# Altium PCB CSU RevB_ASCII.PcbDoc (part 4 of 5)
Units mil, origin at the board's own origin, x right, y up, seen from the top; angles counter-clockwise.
Board outline 5905.51 x 4330.71 mil, 8 copper layers (Top Layer, InternalPlane1, MidLayer1, InternalPlane2, MidLayer2, InternalPlane3, MidLayer3, Bottom Layer); 265 components, 387 nets, 1910 pads, 1151 vias.
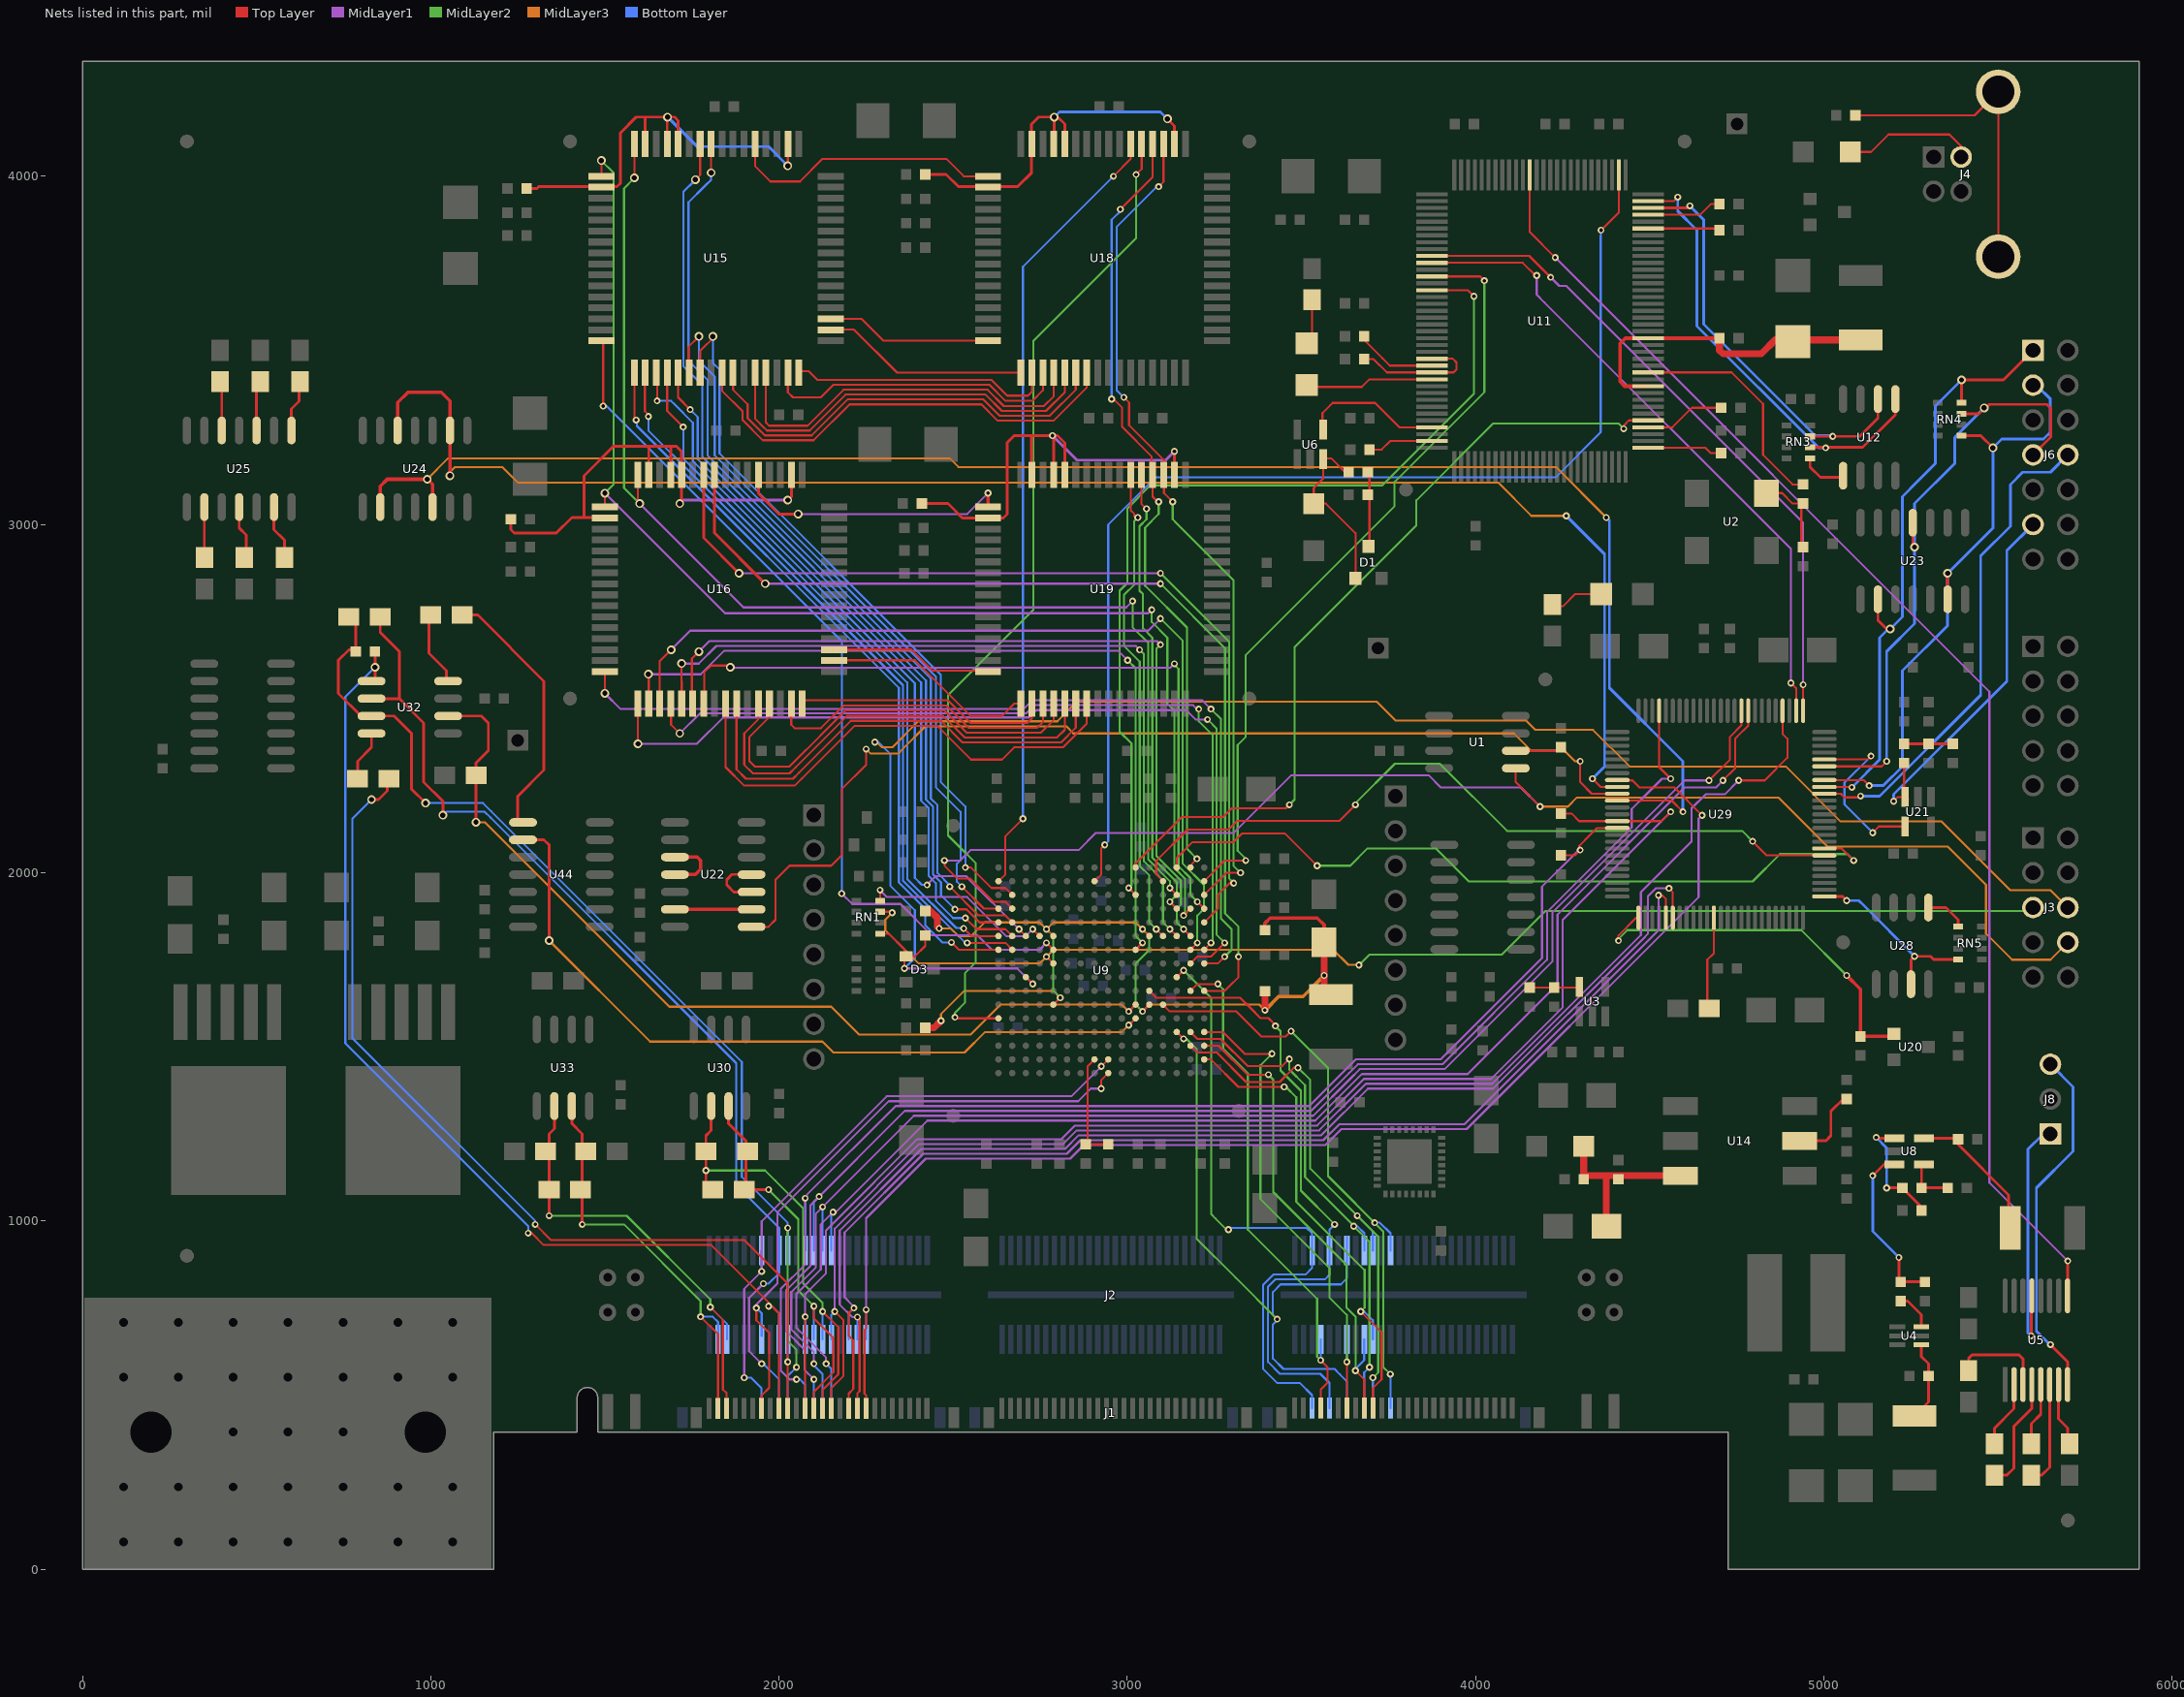
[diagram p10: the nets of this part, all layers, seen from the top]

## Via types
v1: diameter 20, hole 10, Top Layer to Bottom Layer, 647 vias
v2: diameter 25, hole 15, Top Layer to Bottom Layer, 352 vias
v3: diameter 20, hole 10, Top Layer to Bottom Layer, tented top, 151 vias
v4: diameter 20, hole 10, Top Layer to Bottom Layer, tented bottom, 1 vias

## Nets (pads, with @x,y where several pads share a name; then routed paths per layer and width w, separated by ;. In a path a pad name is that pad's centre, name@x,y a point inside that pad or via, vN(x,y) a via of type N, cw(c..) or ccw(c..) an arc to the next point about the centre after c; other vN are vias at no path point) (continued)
MPP: J1.45 J2.45 U9.K15 | length 1502.6
  Top Layer w6: U9.K15@3181.18,1660.67 3200.87,1680.35 v1(3259.92,1680.35) ; v1(3555,600) 3575,580 3575,535 3555,515 3555,463.05 J1.45@3555.21,462.85
  MidLayer2 w6: v1(3259.92,1680.35) 3275,1665.28 3275,1495 3346,1424 3346,974.91 3545,775.91 3545,610 v1(3555,600)
  Bottom Layer w6: v1@3555.51,600.51 J2.45@3555.51,659.84
N_CONFIG: J3.5 RN1.3 U9.H5 | length 3559.7
  Top Layer w6: RN1.3@2290.01,1887.99 2322.01,1887.99 v1(2325,1885) ; v3(2767.8,1759.09) U9.H5@2787.48,1739.41
  MidLayer2 w6: v1(3665,1735) 3695,1765 4075,1765 4200,1890 5590,1890 J3.5@5600,1900
  MidLayer3 w6: v1(2325,1885) 2305,1865 2305,1835 2400.59,1739.41 2748.11,1739.41 2787.48,1778.78 3591.22,1778.78 3634.57,1735.43 3664.57,1735.43 v1(3665,1735)
NCE: C14.1 D3.1 J3.6 RN1.1 U9.J3 | length 5107
  Top Layer w6: RN1.1@2290.01,1825 2315,1825 2360,1780 v1(2360,1725) ; D3.1@2360,1760 2390,1760 2420,1790 C14.1@2420,1820.01 ; U9.J3@2708.74,1700.04 v3(2728.43,1680.35)
  MidLayer1 w6: v1(2360,1725) 2683.78,1725 2716.44,1692.34 v3(2728.43,1680.35)
  MidLayer3 w6: v1(2275,2375) 2280,2375 2295,2360 2325,2360 2400,2435 2799,2435 2855,2491 3715.9,2491 3770,2436.9 4145,2436.9 4171.9,2410 4336.97,2410 4441.97,2305 4890,2305 5048,2147 5338,2147 5535,1950 5650,1950 J3.6@5700,1900
  Bottom Layer w6: v1(2275,2375) 2285,2375 2320,2340 2320,1962.12 2390,1892.12 2390,1755 v1(2360,1725)
NCS: J3.8 U1.1 U9.D2 | length 4069.6
  Top Layer w6: v1(2475,2035) 2475,2020 2512,1983 2549,1983 2615.43,1916.57 2649.68,1916.57 U9.D2@2669.37,1896.89 ; U1.1@4115,2300 4115,2260 v1(4185,2190)
  MidLayer1 w6: v1(2475,2035) 2520,2035 2550,2065 2860,2065 2909.54,2114.54 3305.46,2114.54 3470.91,2280 3865,2280 3900,2245 4130,2245 v1(4185,2190)
  MidLayer3 w6: v1(4185,2190) 4265,2190 4291,2216 4869,2216 5010,2075 5355,2075 5465,1965 5465,1825 5540,1750 5650,1750 J3.8@5700,1800
NetC2_1: C2.1 D1.1 R3.2 U6.3 | length 514.4
  Top Layer w6: R3.2@3635,3150.02 3624.99,3150.01 3585,3190 3564.72,3190 U6.3@3562.4,3187.68 3562.4,3132.4 3535,3105 C2.1@3535,3060 3570,3060 3655,2975 D1.1@3655,2845
NetC5_2: C5.2 J4.E1 J4.E2 | length 912.5
  Top Layer w6: C5.2@5090,4174.99 5432.47,4174.99 J4.E2@5500.39,4242.91 J4.E1@5500.39,3768.9
NetC6_1: C6.1 U5.2 | length 193
  Top Layer w8: C6.1@5490,360 5490,405 5545.59,460.59 U5.2@5545.59,530
NetC6_2: C6.2 U5.4 | length 324.7
  Top Layer w8: C6.2@5490,270 5525,270 5545,290 5545,410 5596.77,461.77 U5.4@5596.77,530
NetC7_1: C7.1 L1.2 U4.4 | length 229.4
  Top Layer w8: L1.2@5260.04,440.12 5300,480.09 5300,590 5279.45,610.55 U4.4@5279.45,644.41
NetC9_1: C9.1 C13.1 L3.2 U11.10 U11.17 | length 997.5
  Top Layer w6: C13.1@4890,3490 4890,3500 4910.22,3520.22 C13.1@4910.22,3524.85 ; L3.2@5099.94,3524.85 L3.2@5104.96,3529.88
  Top Layer w10: U11.10@4495,3397.17 4427.83,3397.17 4415,3410 4415,3520 4429.93,3534.93 C9.1@4700,3534.99
  Top Layer w20: C9.1@4700,3534.99 4700,3500 4710,3490 4820,3490 4860,3530 L3.2@5105,3530
NetC16_1: C16.1 U5.7 | length 183
  Top Layer w8: U5.7@5673.54,530 5673.54,431.46 5700,405 5700,365 C16.1@5705,360
NetC17_1: C17.1 U5.5 | length 181.3
  Top Layer w8: C17.1@5595,360 5595,417.64 5622.36,445 U5.5@5622.36,530
NetC17_2: C17.2 U5.6 | length 299.5
  Top Layer w8: C17.2@5595,270 5625,270 5647.95,292.95 U5.6@5647.95,530
NetC19_1: C19.1 U5.3 | length 283.8
  Top Layer w8: C19.1@5415,560 5415,605 5425,615 5560,615 5571.18,603.82 U5.3@5571.18,530
NetC24_1: C24.1 L4.1 U8.5 | length 430.8
  Top Layer w8: U8.5@5287.32,1237.4 5382.59,1237.4 C24.1@5385,1234.99 5385,1220 5530,1075 5530,970 L4.1@5535,965
NetC31_1: C31.1 C35.2 C38.1 L5.2 U14.6 | length 521.6
  Top Layer w20: L5.2@4310,1215 C35.2@4310,1119.99 4320.01,1130 U14.6@4587.48,1130 ; C31.1@4375,985 4375,1130
NetC74_1: C74.1 R30.2 R32.2 | length 140
  Top Layer w8: R30.2@5230.01,2370 R32.2@5370.01,2370
NetC110_1: C110.1 U29.62 | length 258.4
  Top Layer w6: C110.1@4665,1620 4665,1750 4684.09,1769.09 U29.62@4684.09,1870.51
NetC127_1: C127.1 C128.2 C130.2 C132.2 C134.2 L7.1 U9.F5 U9.F12 U9.L5 U9.L12 | length 2829.6
  Top Layer w6: C134.2@2420,1889.99 C134.2@2420,1899.99 ; v3(2767.8,1837.83) U9.F5@2787.48,1818.15 ; U9.L5@2787.48,1621.3 v3(2807.17,1640.98) ; v3(3043.39,1601.61) U9.L12@3063.07,1621.3 ; v3(3043.39,1837.83) U9.F12@3063.07,1818.15 ; L7.1@3565,1650 L7.1@3595,1650 ; C127.1@3565,1785 C127.1@3565,1795
  Top Layer w10: C128.2@3395,1835.01 3395,1855 3410,1870 3545,1870 3565,1850 C127.1@3565,1795
  Top Layer w20: C132.2@2420,1555 2445,1555 v1(2465,1575) ; C134.2@2420,1889.99 2435.01,1889.99 2455,1870 2455,1845 v1(2460,1840) ; v1(3395,1605) C130.2@3395,1660.01 ; L7.1@3565,1650 v1(3565,1705) C127.1@3565,1785
  MidLayer2 w6: v3(2767.8,1837.83) 2787.48,1818.15 2787.48,1660.67 v3(2807.17,1640.98) ; v3(3043.39,1601.61) 3023.7,1621.3 3023.7,1739.41 3063.07,1778.78 3063.07,1818.15 v3(3043.39,1837.83)
  MidLayer3 w6: v1(2460,1840) 2493.15,1840 2515,1818.15 2551.26,1818.15 2590.63,1857.52 2748.11,1857.52 v3(2767.8,1837.83) 2787.48,1857.52 3023.7,1857.52 v3(3043.39,1837.83) ; v1(2465,1575) 2465,1594.09 2531.57,1660.67 2787.48,1660.67 v3(2807.17,1640.98) ; v3(3043.39,1601.61) 3063.07,1621.3 3378.7,1621.3 v1(3395,1605)
  MidLayer3 w10: v1(3395,1605) 3434.1,1644.1 3504.1,1644.1 v1(3565,1705)
NetD1_3: D1.3 R1.2 R3.1 | length 217.1
  Top Layer w6: R3.1@3690,3150.02 3695,3145.01 D1.3@3695,2935
NetD2_A: D2.A R4.2 | length 131.2
  Top Layer w6: D2.A@3515,3520 3530,3535 R4.2@3530,3645
NetD2_K: D2.K U11.92 | length 360.6
  Top Layer w6: D2.K@3525,3400 3530,3395 3673.15,3395 3695,3416.85 U11.92@3874.45,3416.85
NetD5_A: D5.A R29.1 | length 156.6
  Top Layer w6: R29.1@4220,2770 4225,2765 4250,2765 4285,2800 D5.A@4360,2800
NetJ4_4: J4.4 L2.1 | length 380.6
  Top Layer w6: L2.1@5080,4070 5135,4070 5185,4120 5360,4120 5395,4085 5395,4056.42 J4.4@5393.7,4055.12
NetJ6_11: J6.11 R30.1 U21.3 | length 1111.2
  Top Layer w6: v1(5200,2205) 5212.32,2217.32 U21.3@5232.6,2217.32 U21.3@5230.01,2219.91
  Top Layer w8: R30.1@5230.01,2315 5230.01,2219.99 U21.3@5240,2210
  Bottom Layer w8: v1(5200,2205) 5200,2225 5525,2550 5525,2925 J6.11@5600,3000
NetR2_1: R2.1 U1.2 | length 130
  Top Layer w6: U1.2@4115,2350 R2.1@4245,2350
NetR5_1: R5.1 R6.1 U2.3 | length 249.5
  Top Layer w6: U2.3@4825,3090 4880,3090 4910,3060 4935,3060 4935,2939.99 R5.1@4939.99,2935
NetR6_2: R6.2 U11.12 | length 664
  Top Layer w6: U11.12@4495,3436.54 4735,3436.54 4825,3346.54 4825,3200 4910,3115 R6.2@4940.01,3115
NetR7_1: R7.1 U11.90 | length 235
  Top Layer w6: R7.1@3680,3540.01 3680,3530 3732.77,3477.23 3753.78,3456.22 U11.90@3874.45,3456.22
NetR8_2: R8.2 U11.89 U11.91 | length 379.5
  Top Layer w6: R8.2@3680,3474.99 3706.54,3474.99 3745,3436.54 3936.54,3436.54 3945,3445 3945,3465 3934.09,3475.91 U11.89@3874.45,3475.91
NetR9_2: R9.2 U11.35 | length 217.7
  Top Layer w6: U11.35@4495,3889.29 4644.29,3889.29 4675,3920 R9.2@4700,3920.01
NetR10_2: R10.2 U11.101 | length 189.7
  Top Layer w6: R10.2@3695.01,3215 3730,3215 3754.68,3239.68 U11.101@3874.45,3239.68
NetR11_2: R11.2 U11.4 | length 233.2
  Top Layer w6: U11.4@4495,3279.06 4565,3279.06 4620.94,3335 R11.2@4705,3335.01
NetR12_1: R12.1 R16.1 U3.5 | length 143.6
  Top Layer w6: R16.1@4154.99,1670 4295.28,1670 U3.5@4297.6,1672.32
NetR13_1: R13.1 U4.6 | length 110.7
  Top Layer w8: R13.1@5220.01,770 5240,770 5279.45,730.55 U4.6@5279.45,695.59
NetR13_2: R13.2 R15.2 U8.3 | length 487.6
  Top Layer w8: v1(5140,1130) 5175,1165 U8.3@5205,1165 ; v1(5215,895) 5215,830.01 R13.2@5220.01,825 R15.2@5290.01,825
  Bottom Layer w8: v1(5140,1130) 5140,970 v1(5215,895)
NetR14_2: R14.2 R18.1 U8.4 | length 145
  Top Layer w8: U8.4@5280,1165 R18.1@5280,1095.01 R14.2@5355,1095.01
NetR17_1: R17.1 U11.33 | length 207
  Top Layer w6: U11.33@4495,3849.92 4695.07,3849.92 R17.1@4700,3844.99
NetR18_2: R18.2 R59.1 U8.1 | length 344
  Top Layer w8: v1(5150,1240) 5152.6,1237.4 U8.1@5202.68,1237.4 ; v1(5180,1095) R18.2@5225,1095.01 5280,1040.01 R59.1@5280,1030.01
  Bottom Layer w8: v1(5150,1240) 5180,1210 v1(5180,1095)
NetR19_2: R19.2 R20.2 U9.R8 | length 319.4
  Top Layer w6: U9.R8@2905.59,1463.82 2885.91,1444.13 2885.91,1225.9 R19.2@2880.02,1220 R20.2@2945.01,1220
NetR22_1: R22.1 U11.1 | length 216.2
  Top Layer w6: U11.1@4495,3220 4660,3220 4675,3205 R22.1@4704.99,3205
NetR24_2: R24.2 U14.2 | length 225.7
  Top Layer w8: U14.2@4930,1230 5005,1230 5020,1245 5020,1315 5055,1350 R24.2@5064.99,1350
NetR25_1: R25.1 U15.2 U15.50 U15.60 U15.61 U15.63 | length 1374.6
  Top Layer w6: v2@1678.98,4168.98 v2(1680,4170)
  Top Layer w8: R25.1@1275,3965.01 1305.01,3965.01 1310,3970 1535,3970 1545,3980 1545,4125 1590,4170 1700,4170 1710.47,4159.53 U15.60@1710.47,4093 ; U15.61@1678.98,4093 v2@1678.98,4168.98 ; v2(2025,4030) 2025.43,4030.43 U15.50@2025.43,4093 ; U15.63@1615,4093.98 1615,4170 1615.98,4169.02 U15.63@1615.98,4093 U15.63@1615,4093.98
  Bottom Layer w8: v2(1680,4170) 1765,4085 1970,4085 v2(2025,4030)
NetR26_1: R26.1 U16.2 U16.50 U16.60 U16.61 U16.63 | length 1472.6
  Top Layer w6: 1688.98,3223.98 1690,3225
  Top Layer w8: R26.1@1230,3014.99 1230,2985 1240,2975 1360,2975 1405,3020 1440,3020 ; U16.2@1500,3020 1440,3020 ; U16.63@1625.98,3143 1625.98,3224.02 1625,3225 ; U16.61@1688.98,3143 1688.98,3223.98 1687.95,3225 1625,3225 ; 1690,3225 1705,3225 1720,3210 U16.60@1720,3143.47 ; v2(1715,3060) 1720,3065 U16.60@1720,3143.47 ; U16.60@1720.47,3143 U16.60@1720,3143.47 ; v2(2025,3070) 2035.43,3080.43 U16.50@2035.43,3143 ; 1440,3020 1440,3140 1525,3225 1625,3225
  MidLayer1 w8: v2(1715,3060) 1725,3070 v2(2025,3070)
NetR27_2: R27.2 U18.2 U18.50 U18.60 U18.61 U18.63 | length 1149.8
  Top Layer w8: R27.2@2420,4004.99 2480.01,4004.99 2515,3970 2685,3970 2725,4010 2725,4150 2745,4170 2800,4170 2820.47,4149.53 U18.60@2820.47,4093 ; U18.61@2790,4085 v2(2790,4170) ; v2(3115,4165) 3135.43,4144.57 U18.50@3135.43,4093
  Bottom Layer w8: v2(2790,4170) 2805,4185 3095,4185 v2(3115,4165)
NetR28_1: R28.1 U19.2 U19.50 U19.60 U19.61 U19.63 | length 1428.3
  Top Layer w8: R28.1@2410,3060.01 2485,3060 2526.5,3018.5 2643.5,3018.5 2655,3030 2655,3235 2675,3255 2800,3255 2820.47,3234.53 U19.60@2820.47,3143 ; 2725,3255 2725,3143.98 U19.63@2725.98,3143 ; v1(2785,3255) 2788.98,3251.02 U19.61@2788.98,3143 ; v1(3135,3210) 3135.43,3209.57 U19.50@3135.43,3143
  MidLayer1 w8: v1(2785,3255) 2855,3185 3110,3185 v1(3135,3210)
NetR33_2: R33.2 U25.2 | length 148.5
  Top Layer w6: U25.2@345,3050 U25.2@347.5,3047.5
  Top Layer w8: R33.2@350,2905 U25.2@350,3050
NetR34_2: R34.2 U25.4 | length 155.4
  Top Layer w8: U25.4@450,3050 450,2990 470,2970 470,2910 R34.2@465,2905
NetR35_2: R35.2 U25.6 | length 157.4
  Top Layer w8: U25.6@550,3050 550,2985 580,2955 R35.2@580,2905
NetR36_2: R36.2 U25.8 | length 165
  Top Layer w8: U25.8@600,3270 600,3331.46 622.13,3353.58 622.13,3422.87 R36.2@620,3425
NetR37_2: R37.2 U25.10 | length 144.1
  Top Layer w6: R37.2@500,3400 R37.2@510,3410
  Top Layer w8: U25.10@500,3270 R37.2@500,3400
NetR38_2: R38.2 U25.12 | length 142.1
  Top Layer w6: R38.2@395,3410 R38.2@400,3405
  Top Layer w8: U25.12@400,3270 R38.2@400,3405
NetR45_1: R45.1 U32.4 | length 197.8
  Top Layer w8: R45.1@995,2725 995,2630 1045,2580 1045,2555 U32.4@1050,2550
NetR45_2: R45.2 U44.8 | length 750.2
  Top Layer w8: R45.2@1090,2740 1135,2740 1325,2550 1325,2295 1250,2220 U44.8@1250,2144.57
NetR47_2: R47.2 U32.8 | length 146.6
  Top Layer w8: R47.2@790,2270 790,2320 830,2360 U32.8@830,2400
NetRN3_1: RN3.1 U12.1 | length 134.5
  Top Layer w8: RN3.1@4960.01,3190 4960.01,3164.99 4990,3135 5050,3135 U12.1@5055,3140
NetRN5_1: RN5.1 U28.1 | length 119.5
  Top Layer w8: U28.1@5300,1900 5350,1900 5384.99,1865.01 RN5.1@5384.99,1845
NetRN5_4: RN5.4 U28.7 U29.76 | length 543.1
  Top Layer w8: U29.76@5001.02,1931.54 5053.46,1931.54 v1(5065,1920) ; U28.7@5250,1680 5250,1750 v1(5260,1760) 5305.51,1760 5315,1750.51 RN5.4@5384.99,1750.51
  Bottom Layer w8: v1(5065,1920) 5100,1920 5115,1905 v1(5260,1760)
NetU15_25: U15.25 U18.23 | length 1317.2
  Top Layer w6: U15.25@1836.46,3436 1836.46,3383.54 1895,3325 1895,3300 1953.28,3241.72 2099.4,3241.72 2202.68,3345 2581,3345 2628,3298 2788,3298 2883.46,3393.46 U18.23@2883.46,3436
NetU15_26: U15.26 U18.22 | length 1253.1
  Top Layer w6: U15.26@1867.95,3436 1867.95,3387.05 1910,3345 1910,3305 1924.91,3290.09 1959.28,3255.72 2093.6,3255.72 2196.88,3359 2586.8,3359 2633.8,3312 2777,3312 2851.97,3386.97 U18.22@2851.97,3436
NetU15_28: U15.28 U18.21 | length 1201
  Top Layer w6: U15.28@1930.94,3436 1930.94,3304.06 1957.46,3277.54 ; 1940,3295 1965.28,3269.72 2087.8,3269.72 2191.08,3373 2592.6,3373 2639.6,3326 2766.47,3326 2820.47,3380 U18.21@2820.47,3436
NetU15_29: U15.29 U18.20 | length 1114.9
  Top Layer w6: U15.29@1962.44,3436 1962.44,3292.56 1971.28,3283.72 2082,3283.72 2185.28,3387 2598.4,3387 2645.4,3340 2760,3340 2788.98,3368.98 U18.20@2788.98,3436
NetU15_31: U15.31 U18.19 | length 891.9
  Top Layer w6: U15.31@2025.43,3436 2025.43,3379.57 2040,3365 2120,3365 2156,3401 2604.2,3401 2650.2,3355 2727.48,3355 2757.48,3385 U18.19@2757.48,3436
NetU15_32: U15.32 U18.18 | length 759.3
  Top Layer w6: U15.32@2056.93,3436 2060.93,3440 2085,3440 2110,3415 2610,3415 2655,3370 2715,3370 2725.98,3380.98 U18.18@2725.98,3436
NetU15_34: U15.34 U18.17 | length 598.2
  Top Layer w6: U15.34@2148,3559.06 2148.94,3560 2215,3560 2339,3436 U18.17@2694.49,3436
NetU15_35: U15.35 U18.16 | length 478.1
  Top Layer w6: U15.35@2148,3590.55 2237.01,3590.55 2300,3527.56 U18.16@2600,3527.56
NetU15_53: U15.53 U18.1 | length 798.9
  Top Layer w6: U15.53@1930.94,4093 1930.94,4029.06 1975,3985 2060,3985 2125,4050 2480,4050 2530,4000 U18.1@2600,4000
NetU16_25: U16.25 U19.23 | length 1455.5
  Top Layer w6: U16.25@1845,2484.54 U16.25@1846.46,2486 1846.46,2303.54 1900,2250 2045,2250 2065.54,2270.54 2217,2422 2454,2422 2551,2325 2640,2325 2675,2360 2815,2360 2883.46,2428.46 U19.23@2883.46,2486
NetU16_26: U16.26 U19.22 | length 1355.6
  Top Layer w6: U16.26@1877.95,2486 1877.95,2297.05 1905,2270 2040,2270 2057.51,2287.51 2206,2436 2465,2436 2527,2374 2809.2,2374 2851.97,2416.77 U19.22@2851.97,2486
NetU16_28: U16.28 U19.21 | length 1311.3
  Top Layer w6: U16.28@1940,2495 1940,2440 1900,2400 1900,2310 1925,2285 2030,2285 2047.44,2302.44 2195,2450 2470.8,2450 2532.8,2388 2798,2388 2820.47,2410.47 U19.21@2820.47,2486
NetU16_29: U16.29 U19.20 | length 1225.6
  Top Layer w6: U16.29@1972.44,2486 1972.44,2447.44 1915,2390 1915,2320 1930,2305 2030.2,2305 2039.96,2314.76 2120,2394.8 2120,2395 2191,2466 2474.6,2466 2538.6,2402 2752,2402 2788.98,2438.98 U19.20@2788.98,2486
NetU16_31: U16.31 U19.19 | length 901.6
  Top Layer w6: U16.31@2035.43,2486 2035,2485.57 2035,2425 2045,2415 2120,2415 2185,2480 2480.4,2480 2544.4,2416 2741,2416 2757.48,2432.48 U19.19@2757.48,2486
NetU16_32: U16.32 U19.18 | length 738.1
  Top Layer w6: U16.32@2066.93,2486 2075.93,2495 2485.2,2495 2550.2,2430 2713,2430 2725.98,2442.98 U19.18@2725.98,2486
NetU16_34: U16.34 U19.17 | length 618.1
  Top Layer w6: U16.34@2158,2609.06 2158.94,2610 2390,2610 2550,2450 2640,2450 2676,2486 U19.17@2694.49,2486
NetU16_35: U16.35 U19.16 | length 467.1
  Top Layer w6: U16.35@2158,2640.55 2379.25,2640.55 2439.8,2580 U19.16@2600,2580
NetU16_53: U16.53 U19.1 | length 802.3
  Top Layer w8: U16.53@1940.94,3143 1940.94,3089.06 2000,3030 v2(2055,3030)
  Top Layer w10: U19.1@2600,3050 v1(2600,3090)
  MidLayer1 w6: v2(2055,3030) 2540,3030 v1(2600,3090)
NetU22_2: U22.2 U22.13 | length 220
  Top Layer w10: U22.13@1701.14,1894.57 U22.2@1921.14,1894.57
NetU22_3: U22.3 U22.4 | length 180.8
  Top Layer w8: U22.3@1921.14,1944.57 1870.43,1944.57 1850,1965 1850,1980 1865,1995 U22.4@1930,1995
NetU22_10: U22.10 U22.11 | length 183.4
  Top Layer w10: U22.11@1701.14,1994.57 1701.57,1995 1760,1995 1775,2010 1775,2035 1765,2045 1701.57,2045 U22.10@1701.14,2044.57
NSTATUS: RN1.4 U9.F4 | length 559
  Top Layer w6: RN1.4@2290,1920 v1(2290,1950) ; v3(2728.43,1837.83) U9.F4@2748.11,1818.15
  MidLayer1 w6: v1(2290,1950) 2310,1930 2540,1930 2651.85,1818.15 2708.74,1818.15 v3(2728.43,1837.83)
NTP_PULSE: U9.B16 U11.77 | length 2265.9
  Top Layer w6: U9.B16@3220.55,1975.63 3279.92,2035 v1(3340,2035) ; U11.77@3874.45,3712.13 4012.87,3712.13 v1(4025,3700)
  MidLayer2 w6: v1@3338.66,2036.34 3338.66,2040.89 3316.55,2063 3316.55,2366.55 3340,2390 3340,2625 3767.2,3052.2 3767.2,3122.2 4025,3380 v1(4025,3700)
O_DAT0: U9.C2 U15.23 | length 2119.5
  Top Layer w6: U15.23@1773.46,3436 1773.46,3498.46 1815,3540 v2(1810,3540) ; U15.23@1775,3435 U15.23@1775,3436 ; v1(2535,2015) 2550.94,2015 2610,1955.94 2649.68,1955.94 U9.C2@2669.37,1936.26
  Bottom Layer w6: v2(1810,3540) 1810,3464 1829,3445 1829,3204.19 2464,2569.19 2464,2261 2535,2190 v1(2535,2015)
O_DAT1: U9.D1 U15.22 | length 2151.6
  Top Layer w6: U15.22@1741.97,3437.97 U15.22@1741.97,3436 1740,3437.97 1740,3510 v2(1770,3540) ; v1(2525,1960) 2588.11,1896.89 U9.D1@2630,1896.89
  Bottom Layer w6: v2(1770,3540) 1770,3470 1815,3425 1815,3410 1815,3198.39 2450,2563.39 2450,2246 2521,2175 2521,2036 2510.71,2025.71 2510.71,1974.29 v1(2525,1960)
O_DAT2: U9.F2 U15.21 | length 2084.1
  Top Layer w6: U15.21@1710,3436 1710,3365 v1(1745,3330) ; v1(2535,1870) 2567.17,1837.83 2649.68,1837.83 U9.F2@2669.37,1818.15
  Bottom Layer w6: v1(1745,3330) 1766.6,3308.4 1766.6,3187.4 2408,2545.99 2408,2207 2430,2185 2430,1990 2450,1970 2450,1920 2500,1870 v1(2535,1870)
O_DAT3: U9.F1 U15.20 | length 2083.7
  Top Layer w6: U15.20@1680,3450 1678.98,3448.98 U15.20@1678.98,3436 1678.98,3326.02 v1(1725,3280) ; v1(2530,1840) 2551.85,1818.15 U9.F1@2630,1818.15
  Bottom Layer w6: v1(1725,3280) 1725,3189.4 1746.26,3168.14 2368,2546.4 2368,1982 2508.85,1841.15 2528.85,1841.15 v1(2530,1840)
O_DAT4: U9.F3 U15.19 | length 2190.6
  Top Layer w6: U15.19@1647.48,3436 1650,3433.48 v1(1650,3355) ; v3(2689.06,1837.83) U9.F3@2708.74,1818.15
  MidLayer1 w6: v1(2425,1965) 2450,1990 2536.89,1990 v3(2689.06,1837.83)
  Bottom Layer w6: v1(1650,3355) 1690,3355 1700.9,3344.1 1752.6,3292.4 1752.6,3181.6 2390,2544.2 2390,2070 2390,1985 2410,1965 v1(2425,1965)
O_DAT5: U9.G2 U15.18 | length 2175.4
  Top Layer w6: U15.18@1615,3450 1615,3325 1625,3315 v1(1625,3310) ; v1(2540,1798.46) 2649.68,1798.46 U9.G2@2669.37,1778.78
  Bottom Layer w6: v1(1625,3310) 1625,3269.6 1758.6,3136 2356,2538.6 2356,1977.03 2534.56,1798.46 v1(2540,1798.46)
O_DAT6: U9.G1 U15.17 | length 2172.8
  Top Layer w6: U15.17@1584.49,3436 1584.49,3305.51 v1(1590,3300) ; v1(2495,1800) 2516.22,1778.78 U9.G1@2630,1778.78
  Bottom Layer w6: v1(1590,3300) 1591.97,3298.03 1591.97,3282.83 2344,2530.8 2344,1972.06 2420,1896.06 2420,1849.15 2470,1799.15 2494.15,1799.15 v1(2495,1800)
O_DAT7: U9.G5 U15.16 | length 2569.8
  Top Layer w6: U15.16@1490,3527.56 1495,3522.56 v1(1495,3340) ; v3(2767.8,1798.46) U9.G5@2787.48,1778.78
  MidLayer1 w6: v1(2180,1940) 2210,1910 2348.78,1910 2438.78,1820 2525,1820 2570,1820 2611.22,1778.78 2748.11,1778.78 v3(2767.8,1798.46)
  Bottom Layer w6: v1(1495,3340) 1505,3340 2180,2665 v1(2180,1940)
O_DAT8: U9.D16 U16.23 | length 2188.9
  Top Layer w6: U16.23@1785,2490 1785,2575 1805,2595 1855,2595 v2(1860,2590) ; v3(3200.87,1916.57) U9.D16@3220.55,1896.89
  MidLayer1 w6: v2(1860,2590) 1861,2589 3124,2589 v1(3135,2600)
  MidLayer2 w6: v1(3135,2600) 3135,2597 3147,2585 3147,2018.64 3181.18,1984.46 3181.18,1936.26 v3(3200.87,1916.57)
O_DAT9: U9.F15 U16.22 | length 2386.7
  Top Layer w6: U16.22@1750,2490 1750,2615 v2(1770,2635) ; v3(3161.5,1837.83) U9.F15@3181.18,1818.15
  MidLayer1 w6: v2(1770,2635) 1800,2665 3085,2665 v1(3095,2655)
  MidLayer2 w6: v1(3095,2655) 3083.7,2643.7 3083.7,2048 3153.81,1977.89 3153.81,1908.89 3141.81,1896.89 3141.81,1857.52 v3(3161.5,1837.83)
O_DAT10: U9.F14 U16.21 | length 2320.8
  Top Layer w6: 1720,2550 1720,2600 v2(1720.47,2600.47) ; U16.21@1720.47,2486 1720.47,2550 ; v3(3122.13,1837.83) U9.F14@3141.81,1818.15
  MidLayer1 w6: v2(1720.47,2600.47) 1769.67,2600.47 1820.2,2651 3024,2651 v1(3035,2640)
  MidLayer2 w6: v1(3035,2640) 3047.7,2627.3 3047.7,2032.3 3102.44,1977.56 3102.44,1857.52 v3(3122.13,1837.83)
O_DAT11: U9.G16 U16.20 | length 2346
  Top Layer w6: U16.20@1690,2490 1690,2425 v2(1715,2400) ; U9.G16@3220.55,1778.78 v3(3240.24,1798.46)
  MidLayer1 w6: v2(1715,2400) 1773,2458 2709.6,2458 2732.6,2481 3189,2481 3200,2470 v1(3205,2470)
  MidLayer2 w6: v1(3205,2470) 3205,2435 3244.55,2395.45 3244.55,1802.78 v3(3240.24,1798.46)
O_DAT12: U9.G15 U16.19 | length 2628.9
  Top Layer w6: U16.19@1657.48,2486 1657.48,2607.48 v2(1690,2640) ; U9.G15@3181.18,1778.78 v3(3200.87,1798.46)
  MidLayer1 w6: v2(1690,2640) 1745,2695 3060,2695 v1(3095,2730)
  MidLayer2 w6: v1(3095,2730) 3159,2666 3159,2026.12 3220.12,1965 3220.12,1896.46 3200.87,1877.2 v3(3200.87,1798.46)
O_DAT13: U9.G11 U16.18 | length 2356.3
  Top Layer w6: v2(1625,2570) 1625.98,2569.02 U16.18@1625.98,2486 ; U9.G11@3023.7,1778.78 v3(3043.39,1798.46)
  MidLayer1 w6: v2(1625,2570) 1775,2570 1842,2637 2974,2637 v1(3001,2610)
  MidLayer2 w6: v1(3001,2610) 3023.7,2587.3 3023.7,1818.15 v3(3043.39,1798.46)
O_DAT14: U9.H15 U16.17 | length 2591.3
  Top Layer w6: v2(1595,2370) U16.17@1595,2490 ; U9.H15@3181.18,1739.41 3200.87,1759.09 3240.24,1759.09 v1(3279.61,1798.46)
  MidLayer1 w6: v2(1595,2370) 1764,2370 1840,2446 2717.4,2446 2738.4,2467 3169,2467 3196,2440 v1(3230,2440)
  MidLayer2 w6: v1(3230,2440) 3256.55,2413.45 3256.55,1821.52 v1(3279.61,1798.46)
O_DAT15: U9.H16 U16.16 | length 2655.2
  Top Layer w6: v2(1500,2515) U16.16@1500,2580 ; U9.H16@3220.55,1739.41 3259.92,1739.41 v1(3279.61,1759.09)
  MidLayer1 w6: v2(1500,2515) 1545,2470 2701.8,2470 2726.8,2495 3215,2495 v1(3240,2470)
  MidLayer2 w6: v1(3240,2470) 3268.55,2441.45 3268.55,1868.57 3299.29,1837.83 3299.29,1778.78 v1(3279.61,1759.09)
O_FIFO_AE_H_N: U9.F13 U19.54 | length 1387.4
  Top Layer w6: U19.54@3009.45,3143 3010,3142.45 3010,3040 3020,3030 3020,3025 ; v3(3082.76,1837.83) U9.F13@3102.44,1818.15
  MidLayer2 w6: v1(3030,3020) 3020,3010 3020,2827.21 2990,2797.21 2990,2652 3035.7,2606.3 3035.7,2019.3 3063.07,1991.93 3063.07,1857.52 v3(3082.76,1837.83)
O_FIFO_AE_L_N: U9.B1 U18.54 | length 2276.8
  Top Layer w6: U9.B1@2630,1975.63 2649.68,1995.32 2649.68,2104.68 v1(2700,2155) ; v1(2960,4000) 3010,4050 U18.54@3010,4095
  Bottom Layer w6: v1(2700,2155) 2700,3740 v1(2960,4000)
O_FIFO_AF_H_N: U9.K16 U16.57 | length 2847.5
  Top Layer w6: U16.57@1815,3143 U16.57@1815,3145 ; U9.K16@3220.55,1660.67 3279.61,1660.67 3293.54,1674.6 3318.98,1700.04 v1(3318.98,1759.09)
  Top Layer w8: U16.57@1814.96,3143 1814.96,2975.04 v2(1960,2830)
  MidLayer1 w6: v2(1960,2830) v1(3095,2830)
  MidLayer2 w6: v1(3095,2830) 3280.55,2644.45 3280.55,1883 3318.98,1844.57 v1(3318.98,1759.09)
O_FIFO_AF_L_N: U9.E2 U15.57 | length 2704.4
  Top Layer w6: v2(1805,4010) U15.57@1805,4105 ; v1(2490,1960) 2572.8,1877.2 2649.68,1877.2 U9.E2@2669.37,1857.52
  Bottom Layer w6: v2(1805,4010) 1805,3990 1786.67,3971.67 1740,3925 1740,3470 1794.6,3415.4 1794.6,3198.99 2436,2557.59 2436,2212.94 2455,2193.94 2455,1998.94 2490,1963.94 v1(2490,1960)
O_FIFO_IR_H_N: U9.E16 U16.58 | length 2654.8
  Top Layer w6: U9.E16@3220.55,1857.52 3259.92,1896.89 3259.92,1936.26 v1@3299.29,1975.63
  Top Layer w8: U16.58@1783.47,3143 1783.47,2961.53 v2(1885,2860)
  MidLayer1 w6: v2(1885,2860) v1(3095,2860)
  MidLayer2 w6: v1(3095,2860) 3292.55,2662.45 3292.55,1983 3299.29,1976.26 v1@3299.29,1975.63
  other v1: 3305,1970
O_FIFO_IR_L_N: U9.E1 U15.58 | length 2681.7
  Top Layer w6: v2(1760,3990) 1773.47,4003.47 U15.58@1773.47,4093 ; v1(2505,1895) 2538.03,1895 2575.51,1857.52 U9.E1@2630,1857.52
  Bottom Layer w6: v2(1760,3990) 1725,3955 1725,3455 1780,3400 1780,3193.79 2422,2551.79 2422,2209.97 2442,2189.97 2442,1994.97 2465,1971.97 2465,1935 v1(2505,1895)
O_FIFO_OR_H_N: U9.D14 U19.53 | length 1321.2
  Top Layer w6: U19.53@3040,3120 3040,3060 v1(3055,3045) ; U19.53@3040.94,3120 U19.53@3040.94,3143 ; v3(3122.13,1916.57) U9.D14@3141.81,1896.89
  MidLayer2 w6: v1(3055,3045) 3055,3014.8 3035,2994.8 3035,2810 3045,2800 3045,2701.7 3071.7,2675 3071.7,2043 3141.81,1972.89 3141.81,1936.26 v3(3122.13,1916.57)
O_FIFO_OR_L_N: U9.M1 U18.53 | length 2925.3
  Top Layer w6: v1(2505,1585) 2508.07,1581.93 U9.M1@2630,1581.93 ; v1(3025,4005) 3040.94,4020.94 U18.53@3040.94,4093
  MidLayer2 w6: v1@2506.96,1586.96 v1(2505,1585) 2505,1598.04 2533.63,1626.67 2533.63,1711.63 2565,1743 2565,2027.03 2519.94,2072.09 2485,2107.03 2485,2510 2730,2755 2730,3526.97 2978.74,3775.71 3025,3821.97 v1(3025,4005)
O_FIFO_RCLK: U9.A15 U18.52 U19.52 | length 2280.4
  Top Layer w6: v1(2955,3360) 2960,3360 2985,3335 2985,3280 3070,3195 3070,3137.44 3072.44,3135 3072.44,3080 3087.44,3065 v1(3090,3065) ; v1(2980,3905) 3070.44,3995.44 3072.44,3997.44 U18.52@3072.44,4093 ; U9.A15@3180,2015 3180,2020 v1(3200,2040)
  MidLayer2 w6: v1(3090,3065) 3090,3030 3050.8,2990.8 3050.8,2824.2 3052.28,2822.72 3171,2704 3171,2069 v1(3200,2040)
  Bottom Layer w6: v1(2955,3360) 2955,3875 2985,3905 v1(2980,3905)
O_FIFO_RDEN_N: U9.C16 U18.51 U19.51 | length 2444.2
  Top Layer w6: v1(2990,3365) 3005,3350 3005,3285 3105,3185 U19.51@3105,3145 ; v1(3090,3970) 3103.94,3983.94 U18.51@3103.94,4093 ; U19.51@3103.94,3143 U19.51@3103.94,3145 ; U19.51@3105,3155 3105,3090 v1(3130,3065) ; U9.C16@3220.55,1936.26 3284.29,2000 v1(3325,2000)
  MidLayer2 w6: v1(3130,3065) 3130,3015 3142.02,3002.98 3304.55,2840.45 3304.55,2020.45 v1(3325,2000)
  Bottom Layer w6: v1(2990,3365) 2969,3386 2969,3854 v1@3090,3975
O_FIFO_WCLK: U9.C14 U15.64 U16.64 | length 3591.3
  Top Layer w6: v2(1584.49,3995.51) U15.64@1584.49,4093 ; U16.64@1594.49,3143 1594.49,3065.51 v2(1600,3060) ; v3(3122.13,1955.94) U9.C14@3141.81,1936.26
  MidLayer1 w6: v2(1600,3060) 1898.03,2761.97 2996.97,2761.97 v1(3015,2780)
  MidLayer2 w6: v2(1584.49,3995.51) 1584.49,3994.49 1555,3965 1555,3105 v2(1600,3060) ; v1(3015,2780) 3015,2704.7 3059.7,2660 3059.7,2038 3122.13,1975.57 v3(3122.13,1955.94)
O_FIFO_WREN_N: U9.D15 U15.1 U16.1 | length 3731.9
  Top Layer w6: U15.1@1490,4000 v2(1490,4045) ; U16.1@1500,3050 v2@1500,3095 ; v3(3161.5,1877.2) U9.D15@3181.18,1896.89
  MidLayer1 w6: v2(1500,3090) 1522.67,3067.33 1845,2745 3060,2745 v1(3070,2755)
  MidLayer2 w6: v2(1490,4045) 1525,4010 1525,3115 1505,3095 v2@1500,3095 ; v1(3070,2755) 3070,2720 3115,2675 3115,2485 3135,2465 3135,2013.67 3165.81,1982.86 3165.81,1881.52 v3(3161.5,1877.2)
P1: J1.33 J2.33 U9.R16 | length 1424
  Top Layer w6: U9.R16@3220.55,1463.82 3240,1463.82 3318.82,1385 v1(3450,1385) ; v1(3670,740) 3730,680 3730,545 3705,520 3705,463.05 J1.33@3705.21,462.85
  MidLayer2 w6: v1(3450,1385) 3455,1385 3485,1355 3485,1055 3680,860 3681,860 3681,751 v1(3670,740)
  Bottom Layer w6: v1(3670,740) 3680,740 3705,715 3705,660.35 J2.33@3705.51,659.84
P2: J1.35 J2.35 U9.P16 | length 1388.2
  Top Layer w6: U9.P16@3220.55,1503.19 3261.81,1503.19 3345,1420 v1(3405,1420) ; v1(3655,570) 3680,545 J1.35@3680,465
  MidLayer2 w6: v1(3405,1420) 3419,1406 3419,1083 3613.98,888.02 3628.85,873.15 3628.85,751.45 3655,725.3 v1(3655,570)
  Bottom Layer w6: v1(3655,570) 3655,575 3680,600 3680,659.33 J2.35@3680.51,659.84
P3: J1.39 J2.39 U9.N16 | length 1421.8
  Top Layer w6: U9.N16@3220.55,1542.56 3274.41,1542.56 3336.97,1480 v1(3415,1480) ; J1.39@3630,460 v1(3630,595)
  MidLayer2 w6: v1(3415,1480) 3382,1447 3382,1063 3580,865 3580,780.5 3630,730.5 v1(3630,595)
  Bottom Layer w6: v1(3630,595) 3630.51,595.51 J2.39@3630.51,659.84
PC_RXD: J8.1 U5.13 | length 742.1
  Top Layer w8: v1(5595,670) 5595,786.77 U5.13@5596.77,785
  Bottom Layer w8: v1(5595,670) 5585,680 5585,1205 5630,1250 J8.1@5650,1250
PC_TXD: J8.3 U5.8 | length 1030.3
  Top Layer w8: v1(5650,645) 5699.13,595.87 U5.8@5699.13,530
  Bottom Layer w8: v1(5650,645) 5645,645 5645,648.23 5610,683.23 5610,1095 5715,1200 5715,1385 J8.3@5650,1450
PO_RES_N: U6.4 U11.99 | length 404.1
  Top Layer w6: U6.4@3562.4,3272.32 3560,3274.72 3560,3320 3582.03,3342.03 3588.99,3348.98 3711.01,3348.98 3780.94,3279.06 U11.99@3874.45,3279.06
RD_N: U9.B8 U11.40 | length 3324.4
  Top Layer w6: U9.B8@2905.59,1975.63 2925.28,1995.32 2925.28,2070.28 v1(2935,2080) ; v1(4360,3845) 4411.1,3896.1 U11.40@4411.1,4003.72
  Bottom Layer w6: v1(2935,2080) 2945.16,2090.16 2945.16,2999.47 3080.8,3135.11 4229.2,3135.11 4359.09,3265 4359.09,3830 4360,3830.91 v1(4360,3845)
"RESET BLANK": J1.48 J2.48 U9.J14 | length 1787.7
  Top Layer w6: U9.J14@3141.81,1700.04 v3(3161.5,1719.72)
  MidLayer2 w6: v3(3161.5,1719.72) 3240.69,1640.53 3240.69,1019.31 3253.08,1006.92 3285,975 v1(3290,975)
  Bottom Layer w6: v1(3290,975) 3295,980 3515,980 3530,965 J2.48@3530,915 ; J1.48@3530.21,462.85 3530.21,499.79 3495,535 3429.8,535 3390,574.8 3390,817.3 3418.7,846 3511,846 3530,865 3530,914.45 J2.48@3530.51,914.96
RG: J1.44 J2.44 U9.K12 | length 1876.3
  Top Layer w6: U9.K12@3063.07,1660.67 3082.76,1640.98 3324.02,1640.98 3353.46,1611.54 3382.28,1582.72 3405,1582.72 3425,1562.72 v1(3425,1560)
  MidLayer2 w6: v1(3425,1560) 3440,1545 3440,1432 3498,1374 3498,1087 v1(3595,990)
  Bottom Layer w6: J1.44@3580.21,462.85 3580.21,534.79 3554,561 3438,561 3404,595 3404,811.5 3424.5,832 3567,832 3580,845 3580,914.45 J2.44@3580.51,914.96 3580.51,975.51 v1(3595,990)
RS2+: J1.129 J2.129 R53.2 R55.2 U30.6 | length 1298.6
  Top Layer w6: J1.129@2124.71,461.79 J1.129@2124.71,465 ; J1.129@2125,465 2125,514.8 2170,559.8 2170,695 v1(2125,740)
  Top Layer w8: U30.6@1805,1335 1805,1260 1790,1245 1790,1110 R55.2@1810,1090
  MidLayer2 w6: v1(1790,1145) 1960,1145 1989.07,1115.93 2069,1036 2069,821 2125,765 v1(2125,740)
  Bottom Layer w6: v1(2125,740) 2125.2,739.8 J2.129@2125.2,659.84
RS2-: J1.131 J2.131 R54.1 R55.1 U30.7 | length 1162.4
  Top Layer w6: J1.131@2099.71,461.79 2099.71,509.3 2156,565.6 2156,664 2099.71,720.29 2099.71,754.71 v1(2100,755)
  Top Layer w8: U30.7@1855,1335 1855,1280 1905,1230 1905,1095 R55.1@1900,1090 v1(1970,1090)
  MidLayer2 w6: v1(1970,1090) 2055,1005 2055,800 v1(2100,755) ; v1@2099.71,754.71 v1@2099.71,755.29
  Bottom Layer w6: v1(2100,755) 2100,660.04 J2.131@2100.2,659.84
RS+: J1.151 J2.151 R50.2 R52.2 U33.6 | length 1340.2
  Top Layer w6: v1(1802.71,752.29) 1839,716 1839,516 1849.71,505.29 J1.151@1849.71,461.79
  Top Layer w8: v1(1340,1015) 1340,1250 1355,1265 1355,1335 U33.6@1360,1340
  MidLayer2 w6: v1(1340,1015) 1562.71,1015 1802.71,775 v1(1802.71,752.29)
  Bottom Layer w6: v1(1802.71,752.29) 1850.2,704.8 J2.151@1850.2,659.84
RS-: J1.153 J2.153 R51.1 R52.1 U33.7 | length 1215.6
  Top Layer w6: v1(1775,725) 1825,675 J1.153@1825,465
  Top Layer w8: U33.7@1405,1330 1405,1280 1435,1250 v1(1435,990)
  MidLayer2 w6: v1(1435,990) 1555,990 1775,770 v1(1775,725)
  Bottom Layer w6: v1(1775,725) 1810,725 1825,710 J2.153@1825,675 ; J2.153@1825.2,659.84 J2.153@1825.2,675
RST/NMI_M_N: U21.4 U29.96 | length 523.1
  Top Layer w6: U29.96@5001.02,2325.24 5125.24,2325.24 v1(5135,2335) ; v1(5140,2115) 5157.68,2132.68 U21.4@5232.6,2132.68
  Bottom Layer w6: v1(5135,2335) 5058.83,2258.83 5058.83,2196.17 v1(5140,2115)
RXD_1: U5.9 U11.53 | length 3859
  Top Layer w6: U11.53@4155.2,4003.72 4155.2,3839.8 v1(4228.42,3766.58)
  Top Layer w8: U5.9@5699.13,785 5699.13,884.13 v1(5700,885)
  MidLayer1 w6: v1(4228.42,3766.58) 4235,3760 5475,2520 5475,1110 v1(5700,885)
S1: J1.34 J2.34 U9.P15 | length 1566.3
  Top Layer w6: U9.P15@3181.18,1503.19 3200.87,1483.5 3256.5,1483.5 3341,1399 3437.15,1399 3478.15,1440 v1(3490,1440)
  MidLayer2 w6: v1(3490,1440) 3525,1405 3525,1150 3720,955 3720,565 v1(3705,550)
  Bottom Layer w6: v1(3660,1015) 3705,970 J2.34@3705,915 ; 3705,500 v1(3705,550) ; J1.34@3705.21,462.85 3705.21,500
S2: J1.36 J2.36 U9.N15 | length 1521.5
  Top Layer w6: U9.N15@3181.18,1542.56 3200.87,1522.87 3267.13,1522.87 3345,1445 3445,1445 v1(3465,1465)
  MidLayer2 w6: v1(3465,1465) 3465,1435 3510,1390 3510,1126 v1@3650,986 ; v1(3650,985) 3695,940 v1(3695,580)
  Bottom Layer w6: v1(3650,985) 3660,985 3680.51,964.49 J2.36@3680.51,914.96 ; J1.36@3680,465 3680,565 v1(3695,580)
S3: J1.40 J2.40 U9.N14 | length 1806.8
  Top Layer w6: U9.N14@3141.81,1542.56 v3(3161.5,1522.87)
  MidLayer2 w6: v3(3161.5,1522.87) 3169.82,1522.87 3198.69,1494 3198.69,949.31 3310.92,837.08 v1(3430,718)
  Bottom Layer w6: v1@3430,715 3418,703 3418,605 3448,575 3595,575 3610.6,559.4 3630,540 3630,463.05 J1.40@3630.21,462.85 ; v1(3430,718) 3418,730 3418,796 3440,818 3613,818 3630,835 J2.40@3630,914.96 ; J2.40@3630,914.45 J2.40@3630.51,914.96 ; J2.40@3630,920 J2.40@3630,955
S_WIRED_0: R56.1 U20.1 U29.51 | length 1110.3
  Top Layer w6: v1(4410,1805) 4410,1820 4460,1870 U29.51@4470,1870 ; U20.1@5193.39,1530 U20.1@5200.79,1537.4
  Top Layer w10: v1(5065,1705) 5104.99,1665.01 R56.1@5104.99,1530 U20.1@5193.39,1530
  MidLayer2 w6: v1(4410,1805) 4410,1810 4435,1835 4935,1835 v1(5065,1705)
S_WIRED_1: J1.133 J2.133 R57.1 U29.39 | length 4006.6
  Top Layer w6: J1.133@2074.71,461.79 2074.71,724.71 v1(2075,725) ; R57.1@4244.99,2170 4275,2170 4296.93,2148.07 4533.07,2148.07 v1(4560,2175)
  MidLayer1 w6: v1(2075,725) 2075,790 2135,850 2135,973 2154.05,992.05 2397,1235 2811,1235 2850,1274 3545,1274 3679,1408 4044.06,1408 4250,1613.94 4250,1865 v1(4560,2175)
  Bottom Layer w6: v1(2075,725) 2075.2,724.8 J2.133@2075.2,659.84
S_WIRED_2: J1.134 J2.134 R58.1 U29.40 | length 3842.9
  Top Layer w6: R58.1@4244.99,2050 4285.28,2050 4297.64,2062.36 4297.64,2077.64 4348.39,2128.39 ; 4313.61,2093.61 4348.39,2128.39 ; U29.40@4406.54,2128.39 4348.39,2128.39
  MidLayer1 w6: v1(2050,545) 2030,545 2009.07,565.93 2005,570 2005,805.2 2075,875.2 v1(2075,1065) 2080,1070 2080,1075 2335,1330 3521.81,1330 3636.43,1444.62 3655.81,1464 3899.4,1464 4190.4,1755 4190.4,1960 4295.4,2065 v1(4300,2065)
  Bottom Layer w6: v1(2050,545) 2060,545 2074.71,530.29 J1.134@2074.71,461.79 ; J2.134@2075.2,914.96 v1@2075.2,1064.8
SCL: RN3.3 U11.36 U12.6 | length 1251.1
  Top Layer w8: U11.36@4495,3908.98 4608.98,3908.98 v1(4615,3915) ; RN3.3@4960.01,3252.99 v1(5025,3252.99) 5102.99,3252.99 5155,3305 U12.6@5155,3360
  Bottom Layer w8: v1(4615,3915) 4655,3875 4655,3575 4975,3255 v1@5022.99,3255
SCLK: U24.2 U24.5 U29.36 | length 4907.7
  Top Layer w6: U29.36@4406.54,2207.13 4562.87,2207.13 v1(4595,2175)
  Top Layer w10: U24.2@855,3050 855,3110 875,3130 v2(990,3130) 1005,3115 U24.5@1005,3050
  MidLayer3 w6: v2(990,3130) 1050,3190 2490,3190 2515,3165 4230,3165 v1(4375,3020)
  Bottom Layer w8: v1(4375,3020) 4384,3011 4384,2531 4595,2320 v1(4595,2175)
SDAT: RN3.2 U11.37 U12.5 | length 1326
  Top Layer w6: U11.37@4495,3928.66 4568.66,3928.66 v1(4580,3940) ; U12.5@5205,3350 U12.5@5205,3360
  Top Layer w8: RN3.2@4960.01,3221.5 5111.25,3221.5 5204.75,3315 5204.75,3349.75 U12.5@5205,3350
  Bottom Layer w8: v1(4580,3940) 4580,3900 4635,3845 4635,3570 4985,3220 v1(5005,3220)
SG: J1.30 J2.30 U9.L13 | length 1719.7
  Top Layer w6: U9.L13@3102.44,1621.3 3122.13,1601.61 3313.39,1601.61 3385.15,1529.85 3454.85,1529.85 v1(3470,1545)
  MidLayer2 w6: v1(3470,1545) 3576,1439 3576,1129 3735,970 3735,580 v1(3755,560)
  Bottom Layer w6: v1(3710,995) 3725,995 3755.51,964.49 J2.30@3755.51,914.96 ; v1(3755,560) 3755.21,559.79 J1.30@3755.21,462.85
SHUT_ON: J1.140 J2.140 R46.1 U32.6 | length 2995.5
  Top Layer w8: U32.6@830,2500 910,2500 ; R46.1@855,2735 855,2690 910,2635 910,2500 ; v2(1035,2165) 1035,2205 980,2260 980,2430 910,2500
  MidLayer1 w6: v1(1950,590) 1914,626 1914,779 v1(1955,820)
  Bottom Layer w6: v2(1035,2165) 1045,2175 1155,2175 1172.21,2157.79 1877,1453 1877,1103 2000.2,979.8 J2.140@2000.2,914.96 2000.2,850.2 1970,820 v1(1955,820) ; v1(1950,590) 1955,590 2000,545 2000,490.29 J1.140@1999.71,490 ; J1.140@1999.71,461.79 J1.140@1999.71,490.29
SHUT_STAT: J1.137 J2.137 R47.1 | length 2788.4
  Top Layer w6: v1(1300,990) 1345,945 1900,945 2025,820 2025,705 ; J1.137@2024.71,461.79 2024.71,705
  Top Layer w8: v2(830,2210) 850,2210 875,2235 875,2265 R47.1@870,2270
  Bottom Layer w6: v2(830,2210) 775,2155 775,1525 1300,1000 v1(1300,990) ; J2.137@2025,670 v1(2025,595) v1@2030,590
SHUT_VCC: C141.2 J1.138 J2.138 R46.2 U32.7 | length 3068.1
  Top Layer w8: R46.2@785,2725 785,2640 765,2640 735,2610 735,2515 800,2450 895,2450 945,2400 945,2240 v2(985,2200)
  MidLayer2 w6: v1(2025,980) 2025,655 2050,630 v1(2050,580)
  Bottom Layer w6: v2(985,2200) 1150,2200 1174,2176 1893,1457 1893,1127 2025,995 v1(2025,980) ; J1.138@2024.71,461.79 2024.71,554.71 v1(2050,580) ; J2.138@2025.2,914.96 v1@2025.2,980
SHUTTER_GND: C141.1 J1.139 J2.139 U32.5 | length 3165.1
  Top Layer w6: v1(1280,965) 1290,965 1324,931 1805,931 1970,766 v1(1970,755) 1980,755 1999.71,735.29 J1.139@1999.71,461.79
  Top Layer w8: U32.5@830,2550 840,2560 C141.1@840,2625.01
  Bottom Layer w6: v2(840,2590) 755,2505 755,1510 1280,985 v1(1280,965) ; v1(1970,755) 1980,755 2000.2,734.8 J2.139@2000.2,659.84
SHUTTER_ON_N: U9.M11 U44.9 | length 2218.9
  Top Layer w6: v3(3004.02,1562.24) U9.M11@3023.7,1581.93
  Top Layer w8: U44.9@1260,2095 1325,2095 1340,2080 v2(1340,1805)
  MidLayer3 w6: v2(1340,1805) 1630,1515 2125,1515 2156.5,1483.5 2532.45,1483.5 2591.5,1542.56 2984.33,1542.56 v3(3004.02,1562.24)
SHUTTER_STATUS: R44.1 U9.L11 U32.2 | length 2621.4
  Top Layer w6: v3(3004.02,1601.61) U9.L11@3023.7,1621.3
  Top Layer w8: U32.2@1050,2450 1145,2450 1165.24,2429.76 1165.24,2350.24 1130,2315 v2(1130,2145)
  MidLayer3 w6: v2(1130,2145) 1155,2145 1644.97,1655.03 1685,1615 2150,1615 2230,1535 2550,1535 2636.3,1621.3 2984.33,1621.3 v3(3004.02,1601.61)
SIMO: U24.9 U24.12 U29.34 | length 4643.3
  Top Layer w6: v1(4335,2270) 4358.5,2246.5 U29.34@4406.54,2246.5
  Top Layer w10: U24.12@905,3270 905,3350 935,3380 1030,3380 1055,3355 v2(1055,3140)
  MidLayer3 w6: v2(1055,3140) 1055,3150 1070,3165 1205,3165 1250,3120 4065,3120 4160,3025 v1(4260,3025)
  Bottom Layer w8: v1(4260,3025) 4370,2915 4370,2305 v1(4335,2270)
SLWR_N: U9.A11 U11.5 | length 2326.6
  Top Layer w6: U9.A11@3023.7,2015 3023.7,2027.32 3139.38,2143 3156.39,2160 3275,2160 3300,2185 3455,2185 v1(3465,2195) ; v1(4425,3275) 4425,3283.74 4440,3298.74 U11.5@4495,3298.74
  MidLayer2 w6: v1(3465,2195) 3480,2210 3480,2648.03 3829.74,2997.77 3829.74,3069.74 4050,3290 4410,3290 v1(4425,3275)
SOMI: U22.1 U29.35 | length 3054.7
  Top Layer w6: U22.1@1921.14,1844.57 1969.57,1844.57 1990,1865 1990,1980 2030,2020 2150,2020 2180,2050 2180,2240 2250,2310 v1(2250,2355) ; v1(4300,2320) 4300,2260 4333.19,2226.81 U29.35@4406.54,2226.81
  MidLayer3 w6: v1(2250,2355) 2263.03,2341.97 2341.97,2341.97 2353.94,2353.94 2420,2420 2825,2420 2845,2400 4110,2400 4160,2350 4255,2350 4285,2320 v1(4300,2320)
"SPARE _INPUT_1": J1.143 J2.143 U9.T9 | length 1834
  Top Layer w6: v1@1935,755 1935,715 1971.71,678.29 1971.71,521 1950,499.29 J1.143@1950,460 ; v1@2925.28,1380.28 2925.28,1404.76 U9.T9@2944.96,1424.45
  MidLayer1 w6: v1(1935,750) 1935,760 1995,820 1995,1024 2315,1344 2859,1344 2895,1380 v1(2925,1380)
  Bottom Layer w6: v1(1935,750) 1950,735 J2.143@1950,670
"SPARE _INPUT_2": J1.144 J2.144 U9.R9 | length 1837.6
  Top Layer w6: v3(2925.28,1444.13) U9.R9@2944.96,1463.82
  MidLayer1 w6: v1(1900,550) 1900,805 v1(1950,855) 1950,998.8 2309.2,1358 2839.14,1358 v3(2925.28,1444.13)
  Bottom Layer w6: v1(1900,550) 1920,550 1949.71,520.29 J1.144@1949.71,461.79 ; v1@1950.2,855 J2.144@1950.2,914.96
SWRD_1_SEL_N: J1.127 J2.127 U29.4 | length 4189.1
  Top Layer w6: J1.127@2149.71,461.79 2149.71,519.71 2185,555 2185,715 v1(2160,740) ; v1(4755,2265) 4830,2265 4895,2330 4895,2385 4880.94,2399.06 U29.4@4880.94,2465
  MidLayer1 w6: v1(2160,740) 2160,978.2 2402.8,1221 2816,1221 2855,1260 3550.8,1260 3663.19,1372.38 3684.8,1394 4047.03,1394 4474.37,1821.34 4474.37,1944.37 4620,2090 4620,2185 4660,2225 4715,2225 v1(4755,2265)
  Bottom Layer w6: J2.127@2150.2,659.84 2150.2,730.2 v1(2160,740)
SWRD_2_SEL_N: J1.128 J2.128 U29.9 | length 4175.9
  Top Layer w6: v1(4710,2265) 4745,2300 4745,2385 4750.31,2390.31 4782.52,2422.52 U29.9@4782.52,2465
  MidLayer1 w6: v1(2135,590) 2135,608.05 2050,693.05 2050,790.8 2120,860.8 2120,990 v1(2155,1025) 2163,1025 2426,1288 3539.21,1288 3673.21,1422 3977,1422 4235,1680 4235,1880 4600,2245 4690,2245 v1(4710,2265)
  Bottom Layer w6: v1(2135,590) 2149.71,575.29 J1.128@2149.71,461.79 ; J2.128@2150.2,914.96 2150.2,1020.2 v1(2155,1025)
SWRD_3_SEL_N: J1.130 J2.130 U29.10 | length 4150.8
  Top Layer w6: v1(4670,2265) 4730,2325 4730,2390 4762.83,2422.83 U29.10@4762.83,2465
  MidLayer1 w6: v1(2100,590) 2100,623.25 2035,688.25 2035,795.6 2105,865.6 2105,1020 2387,1302 3533.41,1302 3638.66,1407.26 3667.41,1436 3911,1436 4220,1745 4220,1885 4600,2265 v1(4670,2265)
  Bottom Layer w6: v1(2100,590) 2100,585 2124.71,560.29 J1.130@2124.71,461.79 ; J2.130@2125.2,914.96 v1(2125.2,1040.2)
SWRD_4_SEL_N: J1.132 J2.132 U29.22 | length 4103.1
  Top Layer w6: U29.22@4526.61,2465 4526.61,2303.39 v1(4560,2270)
  MidLayer1 w6: v1(2100,545) 2073.45,571.55 2073.45,630 2021,682.45 2021,801.4 2090,870.4 2090,1045 2361,1316 3527.61,1316 3636.61,1425 3661.61,1450 3904.79,1450 4204.79,1750 4204.79,1886.76 4448.03,2130 4448.03,2183.03 4487.69,2222.69 4515.57,2250.57 4535,2270 v1(4560,2270)
  Bottom Layer w6: J1.132@2099.71,461.79 v1@2099.71,545 ; J2.132@2100.2,914.96 2100.2,1055.2 v1(2115,1070)
SWRD_5_SEL_N: J1.119 J2.119 U29.33 | length 3934.4
  Top Layer w6: J1.119@2249.71,461.79 2249.71,500 2245.21,504.5 2245.21,686.21 2249.71,690.71 2249.71,744.71 v1(2250,745) ; U29.33@4405,2265 4450,2265 4470,2245 4570,2245 v1(4650,2165) ; U29.33@4405.35,2265 U29.33@4406.54,2266.18
  MidLayer1 w6: v1(2250,745) 2250,1008 2421,1179 2836,1179 2875,1218 3568.2,1218 3614.2,1264 3974,1264 4568.63,1858.63 4640,1930 4640,2155 v1(4650,2165)
  Bottom Layer w6: v1(2250,745) 2250.2,744.8 J2.119@2250.2,659.84
SWRD_6_SEL_N: J1.121 J2.121 U29.56 | length 3550.2
  Top Layer w6: J1.121@2224.71,461.79 2224.71,504.71 2231.21,511.21 2231.21,717.64 v1(2225,723.85) ; v1(4555,1955) 4565.98,1944.02 U29.56@4565.98,1870.51
  MidLayer1 w6: v1(2225,723.85) 2210,723.85 2174,759.85 2174,972.4 2408.6,1207 2821,1207 2860,1246 3556.6,1246 3690.6,1380 4050,1380 4478.17,1808.17 4495,1825 4495,1933.03 4516.97,1955 v1(4555,1955)
  Bottom Layer w6: v1(2225,723.85) 2225,660.04 J2.121@2225.2,659.84
SWRD_7_SEL_N: J1.123 J2.123 U29.55 | length 3505.5
  Top Layer w6: J1.123@2199.71,461.79 2200,462.08 2200,504.29 2213.23,517.53 2213.23,656.77 2200,670 2200,735 v1(2215,750) ; v1(4525,1935) 4535,1935 4546.3,1923.7 U29.55@4546.3,1870.51
  MidLayer1 w6: v1(2215,750) 2215,754 2188,781 2188,966.6 2414.4,1193 2826,1193 2865,1232 3562.4,1232 3608.4,1278 3968,1278 4520.11,1830.11 4525,1835 v1(4525,1935)
  Bottom Layer w6: J2.123@2200.2,659.84 2200.2,735.2 v1(2215,750)
TCK_M: J6.7 RN4.3 U23.11 U29.95 | length 1816.3
  Top Layer w6: U29.95@5001.02,2305.55 5165.55,2305.55 v1(5180,2320)
  Top Layer w8: U23.11@5255,3005 5255,2945 5260,2940 v2(5260,2935) ; RN4.3@5395.01,3317.99 5445,3317.99 5460,3332.99 v2(5460,3335) 5465,3335 5475,3345 5640,3345 5651.32,3333.68 5651.32,3251.32 J6.7@5600,3200
  Bottom Layer w8: v1(5180,2320) 5180,2635 5260,2715 5260,3060 5375,3175 5375,3250 v2(5460,3335)
TDI_M: J6.3 RN4.1 U23.6 U29.93 | length 1808.8
  Top Layer w6: U29.93@5001.02,2266.18 5113.82,2266.18 v1(5130,2250)
  Top Layer w8: U23.6@5355,2785 v2(5355,2860) ; RN4.1@5395.01,3255 5450,3255 v2(5485,3220)
  Bottom Layer w6: J6.3@5595,3390 J6.3@5595,3395
  Bottom Layer w8: v1(5130,2250) 5170,2250 5225,2305 5225,2580 5355,2710 v2(5355,2860) 5485,2990 v2(5485,3220) 5510,3245 5630,3245 5650,3265 5650,3360 5615,3395 J6.3@5595,3395
TDO_M: J6.1 RN4.4 U23.2 U29.92 | length 1792
  Top Layer w6: U29.92@5001.02,2246.5 v1@5078.5,2246.5
  Top Layer w8: U23.2@5155,2785 5155,2725 5180,2700 v2(5190,2700) ; RN4.4@5395.01,3349.49 5395.01,3385 v2(5395,3415) 5515,3415 J6.1@5600,3500
  Bottom Layer w8: v1(5080,2245) 5160,2325 5160,2675 5185,2700 v2(5190,2700) 5225,2735 5225,3080 5268.97,3123.97 5320,3175 5320,3340 v2(5395,3415)
TEST: J6.8 U29.91 | length 1415.4
  Top Layer w6: U29.91@5001.02,2226.81 5048.19,2226.81 5058.73,2216.27 5101.27,2216.27 v1(5105,2220)
  Bottom Layer w8: v1(5105,2220) 5160,2220 5450,2510 5450,2910 5535,2995 5535,3115 5570,3150 5650,3150 J6.8@5700,3200
TEST_LINE_1: U11.74 U29.1 | length 1922.9
  Top Layer w6: U11.74@3874.45,3771.18 4153.82,3771.18 v1(4215,3710) ; U29.1@4940,2465 v1(4940,2540)
  MidLayer1 w6: v1(4215,3710) 4240,3685 4260,3685 4940,3005 v1(4940,2540)
TEST_LINE_2: U11.75 U29.2 | length 1874.4
  Top Layer w6: U11.75@3874.45,3751.5 4135,3751.5 v1@4171.5,3715 ; v1(4905,2545) 4920.31,2529.69 U29.2@4920.31,2465
  Top Layer w8: v1@4171.5,3715 v1(4175,3715)
  MidLayer1 w6: v1(4175,3715) 4175,3660 4197.61,3637.39 4905,2930 v1(4905,2545)
TEST_LINE_3: U9.C11 U11.79 | length 2683.1
  Top Layer w6: v3(3004.02,1955.94) U9.C11@3023.7,1936.26 ; U11.79@3874.45,3672.76 3977.24,3672.76 v1(3995,3655)
  MidLayer2 w6: v3(3004.02,1955.94) 3011.7,1963.63 3011.7,2371.3 2978,2405 2978,2810 3000,2832 3000,3046.09 3066.48,3112.57 3732.15,3112.57 3954.72,3335.14 3995,3375.42 v1(3995,3655)
TEST_LINE_4: U9.B13 U29.82 | length 2212.3
  Top Layer w6: U9.B13@3102.44,1975.63 3082.76,1995.32 3082.76,2034.14 3172.61,2124 3289.91,2124 3314.91,2149 3609,2149 v1(3655,2195) ; v1(4795,2090) 4835,2050 4930,2050 ; 4930,2049.65 U29.82@5001.02,2049.65
  MidLayer2 w6: v1(3655,2195) 3655,2200 3768,2313 3897,2313 4090,2120 4765,2120 v1(4795,2090)
TEST_LINE_5: U9.A14 U29.83 | length 2244.5
  Top Layer w6: U9.A14@3141.81,2015 3141.81,2042.29 3187.53,2088 3304.82,2088 3329.82,2113 3452,2113 v1(3545,2020) ; U29.83@5001.02,2069.33 5001.69,2070 5050,2070 v1(5085,2035)
  MidLayer2 w6: v1(3545,2020) 3640,2020 3690,2070 3885,2070 3980,1975 4795,1975 4873.62,2053.62 5066.38,2053.62 v1@5090,2030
